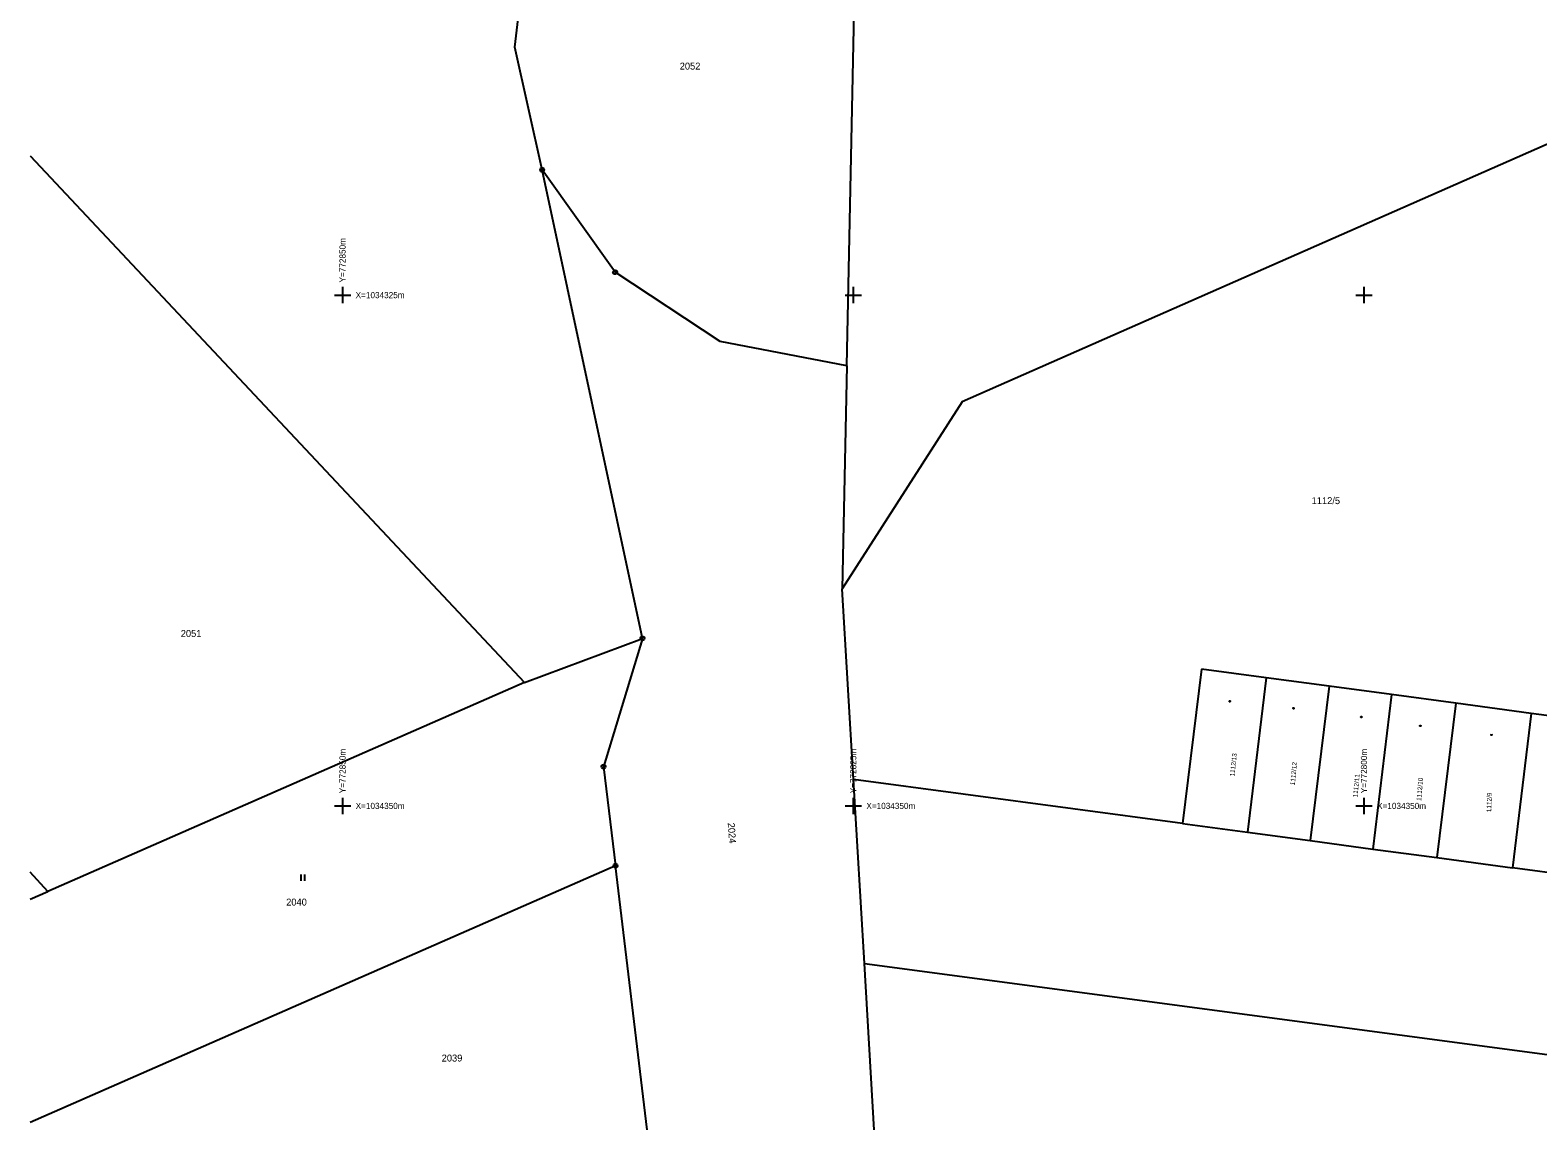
# Model space of a CAD drawing. Extents: x -772865 to -772533, y -1034366 to -1034132.
# Drawn here: x -772865.3 to -772791.5, y -1034365.9 to -1034312 of the extents above; entities that cross this region are included whole.
import ezdxf

# ---------------------------------------------------------------- set-up
doc = ezdxf.new("R2010")
doc.units = 0
for name, color, linetype in [('KM_body', 7, 'Continuous'), ('KM_hranice', 7, 'Continuous'), ('KM_kody_budov', 7, 'Continuous'), ('KM_mezni_znaky', 7, 'Continuous'), ('KM_parcelni_cisla', 7, 'Continuous'), ('KM_popis', 7, 'Continuous'), ('souradnicova_sit', 7, 'Continuous')]:
    doc.layers.add(name, color=color, linetype=linetype)

msp = doc.modelspace()

# ---------------------------------------------------------------- linework, layer by layer
at = {"layer": 'KM_body'}
for p, q in [((-772852.048, -1034353.361), (-772852.048, -1034353.661)), ((-772851.848, -1034353.661), (-772851.848, -1034353.361))]:
    msp.add_line(p, q, dxfattribs=at)
at = {"layer": 'KM_hranice'}
for p, q in [((-772825.31, -1034328.46), (-772824.61, -1034294.49)), ((-772841.56, -1034312.87), (-772840.85, -1034306.77)), ((-772840.23, -1034318.87), (-772841.56, -1034312.87)), ((-772790.73, -1034317.48), (-772819.67, -1034330.22)), ((-772865.29, -1034318.189), (-772841.09, -1034343.96)), ((-772836.66, -1034323.88), (-772840.23, -1034318.87)), ((-772835.31, -1034341.8), (-772840.23, -1034318.87)), ((-772831.52, -1034327.27), (-772836.66, -1034323.88)), ((-772825.31, -1034328.46), (-772831.52, -1034327.27)), ((-772825.31, -1034328.46), (-772825.54, -1034339.38)), ((-772819.67, -1034330.22), (-772825.54, -1034339.38)), ((-772824.99, -1034348.71), (-772825.54, -1034339.38)), ((-772841.09, -1034343.96), (-772835.31, -1034341.8)), ((-772835.31, -1034341.8), (-772837.22, -1034348.08)), ((-772807.95, -1034343.3), (-772808.88, -1034350.86)), ((-772804.79, -1034343.73), (-772807.95, -1034343.3)), ((-772841.09, -1034343.96), (-772864.42, -1034354.19)), ((-772804.79, -1034343.73), (-772805.7, -1034351.29)), ((-772801.71, -1034344.14), (-772804.79, -1034343.73)), ((-772801.71, -1034344.14), (-772802.63, -1034351.7)), ((-772798.65, -1034344.55), (-772801.71, -1034344.14)), ((-772798.65, -1034344.55), (-772799.57, -1034352.11)), ((-772795.51, -1034344.97), (-772798.65, -1034344.55)), ((-772795.51, -1034344.97), (-772796.43, -1034352.53)), ((-772791.81, -1034345.47), (-772795.51, -1034344.97)), ((-772791.81, -1034345.47), (-772792.73, -1034353.03)), ((-772788.44, -1034345.92), (-772791.81, -1034345.47)), ((-772837.22, -1034348.08), (-772836.64, -1034352.93)), ((-772808.88, -1034350.86), (-772824.99, -1034348.71)), ((-772824.45, -1034357.71), (-772824.99, -1034348.71)), ((-772808.88, -1034350.86), (-772805.7, -1034351.29)), ((-772805.7, -1034351.29), (-772802.63, -1034351.7)), ((-772802.63, -1034351.7), (-772799.57, -1034352.11)), ((-772799.57, -1034352.11), (-772796.43, -1034352.53)), ((-772836.64, -1034352.93), (-772865.29, -1034365.494)), ((-772835.085, -1034365.855), (-772836.64, -1034352.93)), ((-772796.43, -1034352.53), (-772792.73, -1034353.03)), ((-772789.36, -1034353.48), (-772792.73, -1034353.03)), ((-772864.42, -1034354.19), (-772865.29, -1034353.236)), ((-772865.29, -1034354.572), (-772864.42, -1034354.19)), ((-772823.968, -1034365.855), (-772824.45, -1034357.71)), ((-772824.45, -1034357.71), (-772763.317, -1034365.855))]:
    msp.add_line(p, q, dxfattribs=at)
at = {"layer": 'KM_kody_budov'}
for points in [[(-772806.57, -1034344.857), (-772806.557, -1034344.86), (-772806.55, -1034344.872), (-772806.547, -1034344.88), (-772806.55, -1034344.892), (-772806.561, -1034344.901), (-772806.57, -1034344.903), (-772806.582, -1034344.899), (-772806.59, -1034344.891), (-772806.593, -1034344.88), (-772806.59, -1034344.868), (-772806.579, -1034344.859)], [(-772803.45, -1034345.197), (-772803.437, -1034345.2), (-772803.43, -1034345.212), (-772803.427, -1034345.22), (-772803.43, -1034345.232), (-772803.441, -1034345.241), (-772803.45, -1034345.243), (-772803.462, -1034345.239), (-772803.47, -1034345.231), (-772803.473, -1034345.22), (-772803.47, -1034345.208), (-772803.459, -1034345.199)], [(-772800.13, -1034345.627), (-772800.117, -1034345.63), (-772800.11, -1034345.642), (-772800.107, -1034345.65), (-772800.11, -1034345.662), (-772800.121, -1034345.671), (-772800.13, -1034345.673), (-772800.142, -1034345.669), (-772800.15, -1034345.661), (-772800.153, -1034345.65), (-772800.15, -1034345.638), (-772800.139, -1034345.629)], [(-772797.24, -1034346.057), (-772797.227, -1034346.06), (-772797.22, -1034346.072), (-772797.217, -1034346.08), (-772797.22, -1034346.092), (-772797.231, -1034346.101), (-772797.24, -1034346.103), (-772797.252, -1034346.099), (-772797.26, -1034346.091), (-772797.263, -1034346.08), (-772797.26, -1034346.068), (-772797.249, -1034346.059)], [(-772793.76, -1034346.497), (-772793.747, -1034346.5), (-772793.74, -1034346.512), (-772793.737, -1034346.52), (-772793.74, -1034346.532), (-772793.751, -1034346.541), (-772793.76, -1034346.543), (-772793.772, -1034346.539), (-772793.78, -1034346.531), (-772793.783, -1034346.52), (-772793.78, -1034346.508), (-772793.769, -1034346.499)]]:
    msp.add_lwpolyline(points, close=True, dxfattribs=at)
at = {"layer": 'KM_mezni_znaky'}
for p, q in [((-772840.254, -1034318.87), (-772840.206, -1034318.87)), ((-772836.684, -1034323.88), (-772836.636, -1034323.88)), ((-772835.334, -1034341.8), (-772835.286, -1034341.8)), ((-772837.244, -1034348.08), (-772837.196, -1034348.08)), ((-772836.664, -1034352.93), (-772836.616, -1034352.93))]:
    msp.add_line(p, q, dxfattribs=at)
for points in [[(-772840.2, -1034318.774), (-772840.15, -1034318.81), (-772840.13, -1034318.868), (-772840.15, -1034318.926), (-772840.2, -1034318.962), (-772840.262, -1034318.962), (-772840.312, -1034318.926), (-772840.332, -1034318.868), (-772840.312, -1034318.81), (-772840.262, -1034318.774)], [(-772836.63, -1034323.784), (-772836.58, -1034323.82), (-772836.56, -1034323.878), (-772836.58, -1034323.936), (-772836.63, -1034323.972), (-772836.692, -1034323.972), (-772836.742, -1034323.936), (-772836.762, -1034323.878), (-772836.742, -1034323.82), (-772836.692, -1034323.784)], [(-772835.28, -1034341.704), (-772835.23, -1034341.74), (-772835.21, -1034341.798), (-772835.23, -1034341.856), (-772835.28, -1034341.892), (-772835.342, -1034341.892), (-772835.392, -1034341.856), (-772835.412, -1034341.798), (-772835.392, -1034341.74), (-772835.342, -1034341.704)], [(-772837.19, -1034347.984), (-772837.14, -1034348.02), (-772837.12, -1034348.078), (-772837.14, -1034348.136), (-772837.19, -1034348.172), (-772837.252, -1034348.172), (-772837.302, -1034348.136), (-772837.322, -1034348.078), (-772837.302, -1034348.02), (-772837.252, -1034347.984)], [(-772836.61, -1034352.834), (-772836.56, -1034352.87), (-772836.54, -1034352.928), (-772836.56, -1034352.986), (-772836.61, -1034353.022), (-772836.672, -1034353.022), (-772836.722, -1034352.986), (-772836.742, -1034352.928), (-772836.722, -1034352.87), (-772836.672, -1034352.834)]]:
    msp.add_lwpolyline(points, close=True, dxfattribs=at)
at = {"layer": 'souradnicova_sit'}
for p, q in [((-772850.4, -1034325), (-772849.6, -1034325)), ((-772850, -1034324.6), (-772850, -1034325.4)), ((-772825.4, -1034325), (-772824.6, -1034325)), ((-772825, -1034324.6), (-772825, -1034325.4)), ((-772800.4, -1034325), (-772799.6, -1034325)), ((-772800, -1034324.6), (-772800, -1034325.4)), ((-772850.4, -1034350), (-772849.6, -1034350)), ((-772850, -1034349.6), (-772850, -1034350.4)), ((-772825.4, -1034350), (-772824.6, -1034350)), ((-772825, -1034349.6), (-772825, -1034350.4)), ((-772800.4, -1034350), (-772799.6, -1034350)), ((-772800, -1034349.6), (-772800, -1034350.4))]:
    msp.add_line(p, q, dxfattribs=at)

# ---------------------------------------------------------------- texts
at = {"layer": 'KM_parcelni_cisla'}
for s, p in [('2052', (-772833.493, -1034313.96)), ('1112/5', (-772802.56, -1034335.23)), ('2051', (-772857.918, -1034341.73)), ('2040', (-772852.758, -1034354.877)), ('2039', (-772845.145, -1034362.512))]:
    msp.add_text(s, height=0.34, dxfattribs=at).set_placement(p)
for s, rotation, p in [('1112/13', 83.76643, (-772806.342, -1034348.567)), ('1112/12', 84.79775, (-772803.383, -1034348.996)), ('1112/11', 84.56857, (-772800.32, -1034349.59)), ('1112/10', 85.4853, (-772797.197, -1034349.761)), ('1112/9', 87.89173, (-772793.776, -1034350.312))]:
    msp.add_text(s, height=0.228, rotation=rotation, dxfattribs=at).set_placement(p)
at = {"layer": 'KM_popis'}
msp.add_text('2024', height=0.34, rotation=273.98842, dxfattribs=at).set_placement((-772831.144, -1034350.836))
at = {"layer": 'souradnicova_sit'}
for s, p in [('Y=772850m', (-772849.85, -1034324.381)), ('Y=772850m', (-772849.85, -1034349.381)), ('Y=772825m', (-772824.85, -1034349.381)), ('Y=772800m', (-772799.85, -1034349.381))]:
    msp.add_text(s, height=0.3, rotation=90.01167, dxfattribs=at).set_placement(p)
for s, p in [('X=1034325m', (-772849.358, -1034325.15)), ('X=1034350m', (-772849.358, -1034350.15)), ('X=1034350m', (-772824.358, -1034350.15)), ('X=1034350m', (-772799.358, -1034350.15))]:
    msp.add_text(s, height=0.3, dxfattribs=at).set_placement(p)

doc.saveas('drawing.dxf')
